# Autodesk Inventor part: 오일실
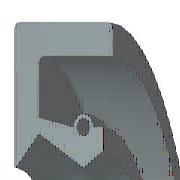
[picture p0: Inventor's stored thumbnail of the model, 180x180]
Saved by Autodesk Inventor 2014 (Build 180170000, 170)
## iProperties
IsCustomPart: 0
Created: 2009-02
Part Number: 오일실
Material: 고무
Description: 오일-실
Document SubType Name: Modeling
Standard: KS B 2804
Designer: KYOUNG IL JANG
Standards Organization: KS
Language: ko-KR
Size Designation: D - 20 32 8
Categories: <MemberInstance><Categories><Category DisplayName="샤프트 부품" InternalName="7f7aeb1f-a693-4053-b835-cee3144e0d98" Mnemonic="SHFT"><Category DisplayName="실링" Intern
Density: 0.93 g/cm^3
Mass: 2.19344 g
Surface Area: 31.4782 cm^2
Volume: 2.35853 cm^3
Appearance: Rubber - Black - Version 1.1
Author: KYOUNG IL JANG
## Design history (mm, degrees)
revolve "본체" stored, may be unused: angle "d17" = 90 deg
revolve "스프링1" stored, may be unused: angle "d18" = 90 deg
body "Solid1"
sketch "스케치1"
  geometry: L1 (0, 16)-(8, 16); L2 (8, 14.25)-(1.75, 14.25); L3 (1.75, 11.75)-(4.9, 10); L4 (4.9, 10)-(0, 10); L5 (0, 0)-(9.586, 0) reference; L6 (4.9, 10)-(6.3, 10.875); L7 (0, 18)-(0, -3) reference; L8 (-1.941, 0)-(11.507, 0) reference; L9 (4.2, 12.1)-(1.75, 12.71); L10 (1.75, 12.71)-(1.75, 14.25); L11 (0, 16)-(0, 10.088); L12 (4.9, 10)-(0, 10); L13 (1.75, 11.75)-(0.152, 10.028); L14 (8, 16)-(8, 14.25); L15 (5.6, 12.1)-(6.3, 12.1); L16 (6.3, 12.1)-(6.3, 10.875); C1 r 0.455 at (4.9, 12.1); A1 r 0.7 centre (4.9, 12.1) between (5.6, 12.1) and (4.2, 12.1); A2 r 0.088 centre (0.088, 10.088) between (0, 10.088) and (0.152, 10.028); 1 further point
  constraints: 28 end point, 5 horizontal alignment, 5 point on line, 4 point on circle, 4 vertical alignment, 3 centre point, 3 tangent, 2 collinear, 2 horizontal, 2 perpendicular, 1 coincident, 1 parallel
  dimensions: "d0" = 32 diameter of L1 L5 (= SD2); "d1" = 1.75 distance of L1.end L2.start (= SD); "d2" = 0.91 diameter of C1 (= SPDI); "d3" = 1.4 diameter of A1 (= SPDA); "d4" = 20 diameter of L3.end L5 (= NND); "d5" = 23.5 diameter of L3.start L5 (= TKDM); "d7" = 25.42 diameter of L9.end L5 (= TKDM + 0.24 x SWDT); "d8" = 1.75 distance between parallel lines of L11 L10 (= SD); "d9" = 4.9 distance from line of L11 C1.centre (= SPDST); "d10" = 24.2 diameter of C1.centre L5 (= HLDM); "d11" = 0.0875 radius of A2 (= 0.25 x LAB); "d12" = 6.3 distance between parallel lines of L11 L16 (= SDI); "d13" = 21.75 diameter of L6.end L5 (= ABDM); "d14" = 8 distance from line of L11 L1.end (= SWDT)
fillet "모깎기1" dims "d6" = 0.3 (= RR)
other parameters: "SD2" = 32 [user parameter; used in 1 equation term], "SWDT" = 8 [user parameter; used in 2 equation terms], "RR" = 0.3 [user parameter; used in 1 equation term], "SD" = 1.75 [user parameter; used in 2 equation terms], "NND" = 20 [user parameter; used in 1 equation term], "SPDA" = 1.4 [user parameter; used in 1 equation term], "SPDI" = 0.91 [user parameter; used in 1 equation term], "TKDM" = 23.5 [user parameter; used in 2 equation terms], "HLDM" = 24.2 [user parameter; used in 1 equation term], "ABDM" = 21.75 [user parameter; used in 1 equation term], "SDI" = 6.3 [user parameter; used in 1 equation term], "SPDST" = 4.9 [user parameter; used in 1 equation term], "LAB" = 0.35 [user parameter; used in 1 equation term], "d15" = 0, "d16" = 0, "d19" = 0
